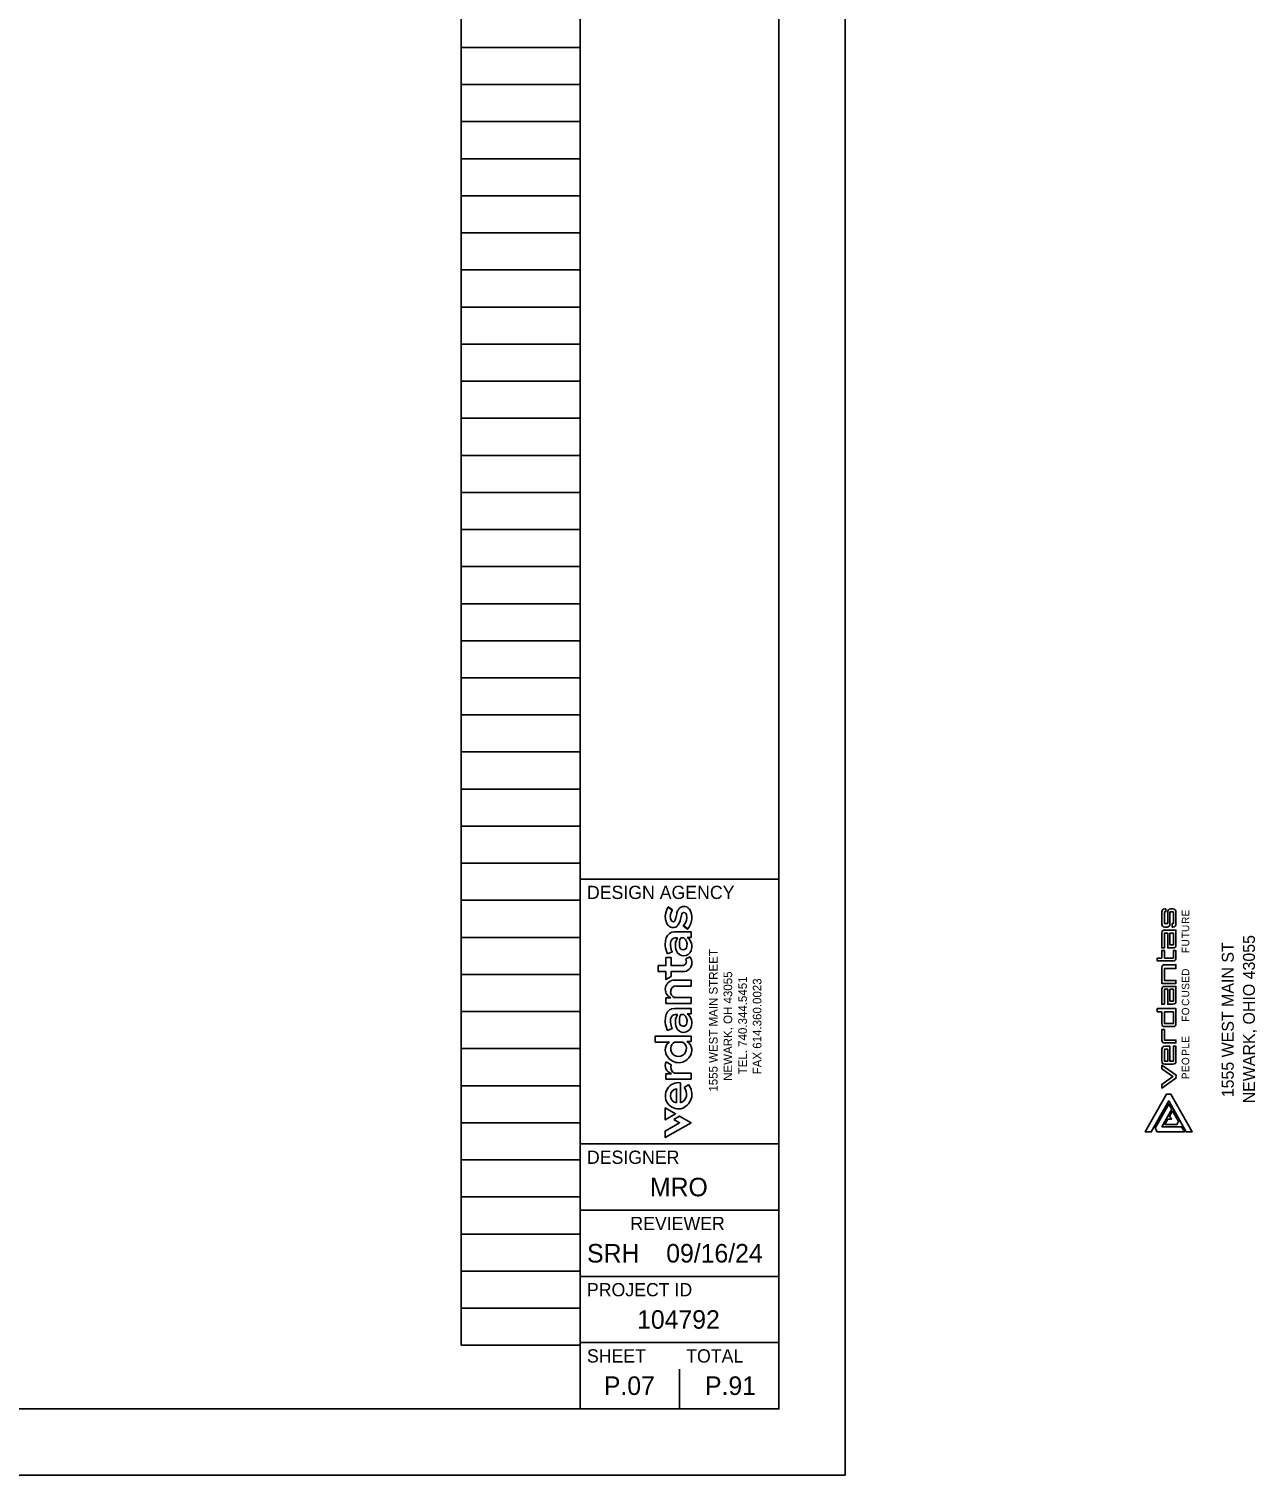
# Model space of a CAD drawing. Extents: x 0 to 37.1, y 0 to 22.
# Drawn here: x 27.83 to 37.11, y 0 to 10.92 of the extents above; entities that cross this region are included whole.
import ezdxf

# ---------------------------------------------------------------- set-up
doc = ezdxf.new("R2010")
doc.units = 0
for name, color, linetype in [('CS-ANNO-TTLB-LOGO', 7, 'Continuous'), ('Default', 7, 'Continuous'), ('SH_Border', 7, 'Continuous'), ('SH_Cut_Line', 7, 'Continuous'), ('SH_Data', 7, 'Continuous'), ('SH_Text', 7, 'Continuous')]:
    doc.layers.add(name, color=color, linetype=linetype)

msp = doc.modelspace()

# ---------------------------------------------------------------- linework, layer by layer
at = {"layer": 'CS-ANNO-TTLB-LOGO'}
for p, q in [((36.423, 4.275), (36.415, 4.275)), ((36.477, 4.275), (36.46, 4.275)), ((36.392, 4.253), (36.392, 4.16)), ((36.499, 4.16), (36.499, 4.253)), ((36.392, 3.98), (36.392, 4.093)), ((36.415, 4.138), (36.432, 4.138)), ((36.392, 3.555), (36.392, 3.668)), ((36.415, 3.387), (36.477, 3.387)), ((36.392, 3.215), (36.392, 3.125)), ((36.499, 3.125), (36.499, 3.238)), ((36.415, 3.103), (36.477, 3.103))]:
    msp.add_line(p, q, dxfattribs=at)
for points in [[(36.437, 4.253), (36.437, 4.166), (36.412, 4.166), (36.412, 4.253), (36.423, 4.253), (36.423, 4.275)], [(36.454, 4.16), (36.454, 4.253), (36.48, 4.253), (36.48, 4.166), (36.471, 4.166), (36.471, 4.138), (36.477, 4.138)], [(36.477, 3.98), (36.437, 3.98), (36.437, 4.093), (36.412, 4.093), (36.412, 3.98), (36.392, 3.98)], [(36.415, 4.115), (36.499, 4.115), (36.499, 4.003)], [(36.358, 3.904), (36.392, 3.904), (36.392, 3.96), (36.412, 3.96), (36.412, 3.904), (36.48, 3.904), (36.48, 3.96), (36.499, 3.96), (36.499, 3.904)], [(36.477, 3.882), (36.358, 3.882), (36.358, 3.904)], [(36.392, 3.831), (36.392, 3.713), (36.499, 3.713), (36.499, 3.735), (36.412, 3.735), (36.412, 3.825), (36.499, 3.825)], [(36.499, 3.825), (36.499, 3.853), (36.415, 3.853)], [(36.477, 3.555), (36.437, 3.555), (36.437, 3.668), (36.412, 3.668), (36.412, 3.555), (36.392, 3.555)], [(36.415, 3.69), (36.499, 3.69), (36.499, 3.578)], [(36.358, 3.522), (36.358, 3.499), (36.392, 3.499), (36.392, 3.409)], [(36.499, 3.409), (36.499, 3.522), (36.358, 3.522)], [(36.499, 3.285), (36.412, 3.285), (36.412, 3.364), (36.392, 3.364), (36.392, 3.285)], [(36.415, 3.263), (36.499, 3.263), (36.499, 3.285)], [(36.499, 3.238), (36.48, 3.238), (36.48, 3.125), (36.454, 3.125), (36.454, 3.238), (36.415, 3.238)]]:
    msp.add_lwpolyline(points, dxfattribs=at)
for points in [[(36.454, 4.093), (36.48, 4.093), (36.48, 4.003), (36.454, 4.003)], [(36.454, 3.668), (36.48, 3.668), (36.48, 3.578), (36.454, 3.578)], [(36.412, 3.499), (36.412, 3.409), (36.48, 3.409), (36.48, 3.499)], [(36.437, 3.215), (36.412, 3.215), (36.412, 3.125), (36.437, 3.125)], [(36.477, 3.009), (36.392, 2.95), (36.392, 2.922), (36.499, 2.997), (36.5, 3.02), (36.393, 3.095), (36.392, 3.068)]]:
    msp.add_lwpolyline(points, close=True, dxfattribs=at)
for centre, start, end in [((36.415, 4.253), 90, 180), ((36.46, 4.253), 90, 180), ((36.477, 4.253), 360, 90), ((36.415, 4.16), 180, 270), ((36.432, 4.16), 270, 0), ((36.477, 4.16), 270, 0), ((36.415, 4.093), 90, 180), ((36.477, 4.003), 270, 360), ((36.415, 3.831), 90, 180), ((36.477, 3.904), 270, 360), ((36.415, 3.668), 90, 180), ((36.477, 3.578), 270, 360), ((36.415, 3.409), 180, 270), ((36.477, 3.409), 270, 0), ((36.415, 3.285), 180, 270), ((36.415, 3.215), 90, 180), ((36.415, 3.125), 180, 270), ((36.477, 3.125), 270, 0)]:
    msp.add_arc(centre, 0.0225, start, end, dxfattribs=at)
at = {"layer": 'Default'}
for p, q in [((36.477, 4.275), (36.46, 4.275)), ((36.392, 4.253), (36.392, 4.16)), ((36.499, 4.16), (36.499, 4.253)), ((36.415, 4.138), (36.432, 4.138)), ((36.415, 3.387), (36.477, 3.387)), ((36.392, 3.215), (36.392, 3.125)), ((36.415, 3.103), (36.477, 3.103)), ((36.342, 2.619), (36.445, 2.802)), ((36.468, 2.762), (36.394, 2.63)), ((36.445, 2.802), (36.468, 2.762)), ((36.394, 2.63), (36.542, 2.63)), ((36.542, 2.63), (36.564, 2.591)), ((36.358, 2.591), (36.342, 2.619)), ((36.564, 2.591), (36.358, 2.591))]:
    msp.add_line(p, q, dxfattribs=at)
for points in [[(36.437, 4.253), (36.437, 4.166), (36.412, 4.166), (36.412, 4.253), (36.423, 4.253), (36.423, 4.275), (36.415, 4.275)], [(36.454, 4.16), (36.454, 4.253), (36.48, 4.253), (36.48, 4.166), (36.471, 4.166), (36.471, 4.138), (36.477, 4.138)], [(36.392, 4.093), (36.392, 3.98), (36.412, 3.98), (36.412, 4.093), (36.437, 4.093), (36.437, 3.98), (36.477, 3.98)], [(36.499, 4.003), (36.499, 4.115), (36.415, 4.115)], [(36.499, 3.904), (36.499, 3.96), (36.48, 3.96), (36.48, 3.904), (36.412, 3.904), (36.412, 3.96), (36.392, 3.96), (36.392, 3.904), (36.358, 3.904), (36.358, 3.882), (36.477, 3.882)], [(36.392, 3.831), (36.392, 3.713), (36.499, 3.713), (36.499, 3.735), (36.412, 3.735), (36.412, 3.825), (36.499, 3.825), (36.499, 3.853), (36.415, 3.853)], [(36.392, 3.668), (36.392, 3.555), (36.412, 3.555), (36.412, 3.668), (36.437, 3.668), (36.437, 3.555), (36.477, 3.555)], [(36.499, 3.578), (36.499, 3.69), (36.415, 3.69)], [(36.499, 3.409), (36.499, 3.522), (36.358, 3.522), (36.358, 3.499), (36.392, 3.499), (36.392, 3.409)], [(36.415, 3.263), (36.499, 3.263), (36.499, 3.285), (36.412, 3.285), (36.412, 3.364), (36.392, 3.364), (36.392, 3.285)], [(36.499, 3.125), (36.499, 3.238), (36.48, 3.238), (36.48, 3.125), (36.454, 3.125), (36.454, 3.238), (36.415, 3.238)]]:
    msp.add_lwpolyline(points, dxfattribs=at)
for points in [[(36.48, 4.093), (36.48, 4.003), (36.454, 4.003), (36.454, 4.093)], [(36.48, 3.668), (36.48, 3.578), (36.454, 3.578), (36.454, 3.668)], [(36.412, 3.499), (36.48, 3.499), (36.48, 3.409), (36.412, 3.409)], [(36.437, 3.215), (36.437, 3.125), (36.412, 3.125), (36.412, 3.215)], [(36.392, 2.95), (36.392, 2.922), (36.499, 2.997), (36.5, 3.02), (36.393, 3.095), (36.392, 3.068), (36.477, 3.009)], [(36.445, 2.825), (36.577, 2.591), (36.622, 2.591), (36.461, 2.876), (36.429, 2.876), (36.268, 2.591), (36.313, 2.591)], [(36.313, 2.591), (36.445, 2.825), (36.577, 2.591), (36.622, 2.591), (36.461, 2.876), (36.429, 2.876), (36.268, 2.591)], [(36.342, 2.619), (36.358, 2.591), (36.564, 2.591), (36.542, 2.63), (36.394, 2.63), (36.468, 2.762), (36.445, 2.802)], [(36.438, 2.687), (36.416, 2.647), (36.507, 2.647), (36.519, 2.67), (36.474, 2.75), (36.452, 2.71), (36.465, 2.687)], [(36.438, 2.687), (36.465, 2.687), (36.452, 2.71), (36.474, 2.75), (36.519, 2.67), (36.507, 2.647), (36.416, 2.647)]]:
    msp.add_lwpolyline(points, close=True, dxfattribs=at)
for centre, start, end in [((36.415, 4.253), 90, 180), ((36.46, 4.253), 90, 180), ((36.477, 4.253), 360, 90), ((36.415, 4.16), 180, 270), ((36.432, 4.16), 270, 0), ((36.477, 4.16), 270, 0), ((36.415, 4.093), 90, 180), ((36.477, 4.003), 270, 0), ((36.415, 3.831), 90, 180), ((36.477, 3.904), 270, 0), ((36.415, 3.668), 90, 180), ((36.477, 3.578), 270, 0), ((36.415, 3.409), 180, 270), ((36.477, 3.409), 270, 0), ((36.415, 3.285), 180, 270), ((36.415, 3.215), 90, 180), ((36.415, 3.125), 180, 270), ((36.477, 3.125), 270, 0)]:
    msp.add_arc(centre, 0.0225, start, end, dxfattribs=at)
at = {"layer": 'SH_Border'}
for p, q in [((32, 0.5), (32, 21.5)), ((32, 4.5), (33.5, 4.5)), ((32, 2.5), (33.5, 2.5)), ((32, 2), (33.5, 2)), ((32, 1.5), (33.5, 1.5)), ((32, 1), (33.5, 1))]:
    msp.add_line(p, q, dxfattribs=at)
msp.add_lwpolyline([(1.5, 21.5), (33.5, 21.5), (33.5, 0.5), (1.5, 0.5)], close=True, dxfattribs=at)
at = {"layer": 'SH_Cut_Line'}
msp.add_lwpolyline([(0, 0), (34, 0), (34, 22), (0, 22)], close=True, dxfattribs=at)
at = {"layer": 'SH_Data'}
for p, q in [((31.1, 0.98), (31.1, 21.14)), ((32, 0.98), (32, 21.14)), ((31.1, 10.78), (32, 10.78)), ((31.1, 10.5), (32, 10.5)), ((31.1, 10.22), (32, 10.22)), ((31.1, 9.94), (32, 9.94)), ((31.1, 9.66), (32, 9.66)), ((31.1, 9.38), (32, 9.38)), ((31.1, 9.1), (32, 9.1)), ((31.1, 8.82), (32, 8.82)), ((31.1, 8.54), (32, 8.54)), ((31.1, 8.26), (32, 8.26)), ((31.1, 7.98), (32, 7.98)), ((31.1, 7.7), (32, 7.7)), ((31.1, 7.42), (32, 7.42)), ((31.1, 7.14), (32, 7.14)), ((31.1, 6.86), (32, 6.86)), ((31.1, 6.58), (32, 6.58)), ((31.1, 6.3), (32, 6.3)), ((31.1, 6.02), (32, 6.02)), ((31.1, 5.74), (32, 5.74)), ((31.1, 5.46), (32, 5.46)), ((31.1, 5.18), (32, 5.18)), ((31.1, 4.9), (32, 4.9)), ((31.1, 4.62), (32, 4.62)), ((31.1, 4.34), (32, 4.34)), ((31.1, 4.06), (32, 4.06)), ((31.1, 3.78), (32, 3.78)), ((31.1, 3.5), (32, 3.5)), ((32.75, 3.5), (32.75, 3.5)), ((31.1, 3.22), (32, 3.22)), ((31.1, 2.94), (32, 2.94)), ((31.1, 2.66), (32, 2.66)), ((31.1, 2.38), (32, 2.38)), ((31.1, 2.1), (32, 2.1)), ((31.1, 1.82), (32, 1.82)), ((31.1, 1.54), (32, 1.54)), ((31.1, 1.26), (32, 1.26)), ((31.1, 0.98), (32, 0.98)), ((32.75, 0.5), (32.75, 0.8)), ((32.375, 0.675), (32.375, 0.675))]:
    msp.add_line(p, q, dxfattribs=at)
at = {"layer": 'SH_Text'}
for p, q in [((32.694, 4.265), (32.663, 4.288)), ((32.728, 4.239), (32.722, 4.208)), ((32.757, 4.197), (32.762, 4.217)), ((32.717, 4.057), (32.733, 4.057)), ((32.759, 4.057), (32.782, 4.057)), ((32.78, 4.149), (32.813, 4.125)), ((32.654, 3.949), (32.658, 3.937)), ((32.831, 3.913), (32.796, 3.897)), ((32.717, 3.478), (32.733, 3.478)), ((32.759, 3.478), (32.782, 3.478)), ((32.654, 3.37), (32.658, 3.358)), ((32.712, 3.27), (32.772, 3.27)), ((32.685, 3.099), (32.648, 3.121)), ((32.757, 2.81), (32.757, 2.963)), ((32.727, 2.918), (32.727, 2.811)), ((32.817, 2.948), (32.784, 2.926))]:
    msp.add_line(p, q, dxfattribs=at)
for points in [[(32.696, 4.267), (32.664, 4.29), (32.663, 4.288)], [(32.694, 4.265), (32.696, 4.267)], [(32.728, 4.239), (32.722, 4.208)], [(32.757, 4.197), (32.762, 4.217)], [(32.807, 4.06), (32.837, 4.06), (32.837, 4.102), (32.712, 4.102)], [(32.807, 4.06), (32.837, 4.06), (32.837, 4.102), (32.712, 4.102)], [(32.717, 4.057), (32.733, 4.057)], [(32.782, 4.057), (32.759, 4.057)], [(32.78, 4.149), (32.778, 4.147), (32.809, 4.122), (32.813, 4.125)], [(32.654, 3.949), (32.658, 3.937)], [(32.658, 3.937), (32.694, 3.951), (32.69, 3.96)], [(32.658, 3.937), (32.694, 3.951), (32.69, 3.96)], [(32.768, 3.847), (32.686, 3.847), (32.686, 3.908), (32.647, 3.908), (32.647, 3.847), (32.589, 3.847), (32.589, 3.802), (32.647, 3.802), (32.647, 3.742), (32.686, 3.765), (32.686, 3.802), (32.776, 3.802)], [(32.768, 3.847), (32.686, 3.847), (32.686, 3.908), (32.647, 3.908), (32.647, 3.847), (32.589, 3.847), (32.589, 3.802), (32.647, 3.802), (32.647, 3.742), (32.686, 3.765), (32.686, 3.802), (32.776, 3.802)], [(32.831, 3.913), (32.796, 3.897)], [(32.726, 3.693), (32.837, 3.693), (32.837, 3.738), (32.713, 3.738)], [(32.726, 3.693), (32.837, 3.693), (32.837, 3.738), (32.713, 3.738)], [(32.684, 3.603), (32.647, 3.603), (32.647, 3.561), (32.837, 3.561), (32.837, 3.607), (32.71, 3.607)], [(32.684, 3.603), (32.647, 3.603), (32.647, 3.561), (32.837, 3.561), (32.837, 3.607), (32.71, 3.607)], [(32.807, 3.482), (32.837, 3.482), (32.837, 3.524), (32.712, 3.524)], [(32.807, 3.482), (32.837, 3.482), (32.837, 3.524), (32.712, 3.524)], [(32.717, 3.478), (32.733, 3.478)], [(32.782, 3.478), (32.759, 3.478)], [(32.673, 3.27), (32.566, 3.27), (32.566, 3.315), (32.837, 3.315), (32.837, 3.274), (32.804, 3.274)], [(32.804, 3.274), (32.837, 3.274), (32.837, 3.315), (32.566, 3.315), (32.566, 3.27), (32.673, 3.27)], [(32.654, 3.37), (32.658, 3.358)], [(32.658, 3.358), (32.694, 3.373), (32.69, 3.382)], [(32.658, 3.358), (32.694, 3.373), (32.69, 3.382)], [(32.712, 3.27), (32.772, 3.27)], [(32.685, 3.099), (32.648, 3.121)], [(32.688, 3.031), (32.647, 3.031), (32.647, 2.99), (32.837, 2.99), (32.837, 3.034), (32.711, 3.034)], [(32.688, 3.031), (32.647, 3.031), (32.647, 2.99), (32.837, 2.99), (32.837, 3.034), (32.711, 3.034)], [(32.757, 2.81), (32.757, 2.963)], [(32.727, 2.811), (32.727, 2.918)], [(32.817, 2.948), (32.784, 2.926)], [(32.642, 2.773), (32.642, 2.682), (32.72, 2.728), (32.642, 2.773)], [(32.706, 2.686), (32.75, 2.66), (32.642, 2.598), (32.642, 2.548), (32.837, 2.66), (32.749, 2.711), (32.706, 2.686)]]:
    msp.add_lwpolyline(points, dxfattribs=at)
for points in [[(32.72, 2.728), (32.642, 2.682), (32.642, 2.773)], [(32.706, 2.686), (32.75, 2.66), (32.642, 2.598), (32.642, 2.548), (32.837, 2.66), (32.749, 2.711)]]:
    msp.add_lwpolyline(points, close=True, dxfattribs=at)
for centre, radius, start, end in [((32.773, 4.217), 0.131, 147.2233, 179.842), ((32.773, 4.217), 0.131, 147.2233, 179.842), ((32.774, 4.215), 0.0948, 148.1233, 178.1135), ((32.774, 4.215), 0.0948, 148.1233, 178.1135), ((32.855, 4.21), 0.13, 154.0447, 167.2149), ((32.855, 4.21), 0.13, 154.0447, 167.2149), ((32.783, 4.245), 0.0493, 52.7092, 154.2166), ((32.783, 4.245), 0.0493, 52.7092, 154.2166), ((32.767, 4.23), 0.0711, 22.8278, 50.7157), ((32.767, 4.23), 0.0711, 22.8278, 50.7157), ((32.756, 4.216), 0.114, 179.0109, 203.56), ((32.756, 4.216), 0.114, 179.0109, 203.56), ((32.713, 4.197), 0.067, 203.3692, 237.807), ((32.713, 4.197), 0.067, 203.3692, 237.807), ((32.75, 4.216), 0.0702, 179.0539, 195.6921), ((32.75, 4.216), 0.0702, 179.0539, 195.6921), ((32.715, 4.206), 0.0335, 193.8561, 223.7191), ((32.715, 4.206), 0.0335, 193.8561, 223.7191), ((32.701, 4.193), 0.0148, 224.7822, 330.4366), ((32.701, 4.193), 0.0148, 224.7822, 330.4366), ((32.641, 4.223), 0.0819, 332.9002, 349.3831), ((32.641, 4.223), 0.0819, 332.9002, 349.3831), ((32.654, 4.216), 0.105, 320.1259, 349.7023), ((32.654, 4.216), 0.105, 320.1259, 349.7023), ((32.855, 4.202), 0.0949, 158.1863, 170.6328), ((32.855, 4.202), 0.0949, 158.1863, 170.6328), ((32.783, 4.232), 0.0165, 26.9165, 163.602), ((32.783, 4.232), 0.0165, 26.9165, 163.602), ((32.712, 4.212), 0.0932, 317.363, 356.9244), ((32.712, 4.212), 0.0932, 317.363, 356.9244), ((32.739, 4.211), 0.0655, 357.0077, 26.3112), ((32.739, 4.211), 0.0655, 357.0077, 26.3112), ((32.713, 4.208), 0.129, 320.5166, 0.4341), ((32.713, 4.208), 0.129, 320.5166, 0.4341), ((32.723, 4.211), 0.12, 359.0192, 22.9257), ((32.723, 4.211), 0.12, 359.0192, 22.9257), ((32.77, 4.015), 0.128, 160.8128, 180.9317), ((32.77, 4.015), 0.128, 160.8128, 180.9317), ((32.71, 4.038), 0.0639, 88.076, 162.8642), ((32.71, 4.038), 0.0639, 88.076, 162.8642), ((32.701, 4.179), 0.0458, 238.9453, 317.6829), ((32.701, 4.179), 0.0458, 238.9453, 317.6829), ((32.719, 4.019), 0.0374, 92.9671, 165.223), ((32.719, 4.019), 0.0374, 92.9671, 165.223), ((32.826, 4), 0.108, 148.3497, 202.4708), ((32.826, 4), 0.108, 148.3497, 202.4708), ((32.853, 4.01), 0.105, 153.8372, 188.8746), ((32.853, 4.01), 0.105, 153.8372, 188.8746), ((32.743, 4.006), 0.0637, 348.1247, 52.3678), ((32.743, 4.006), 0.0637, 348.1247, 52.3678), ((32.757, 3.991), 0.0857, 338.2774, 53.7949), ((32.757, 3.991), 0.0857, 338.2774, 53.7949), ((32.84, 4.016), 0.199, 180.9467, 199.8354), ((32.84, 4.016), 0.199, 180.9467, 199.8354), ((32.745, 4.01), 0.0647, 163.2522, 179.9971), ((32.745, 4.01), 0.0647, 163.2522, 179.9971), ((32.832, 4.014), 0.152, 181.6616, 200.8714), ((32.832, 4.014), 0.152, 181.6616, 200.8714), ((32.781, 3.98), 0.0592, 201.6764, 339.7268), ((32.781, 3.98), 0.0592, 201.6764, 339.7268), ((32.777, 3.995), 0.0281, 182.327, 355.3778), ((32.777, 3.995), 0.0281, 182.327, 355.3778), ((32.77, 3.878), 0.0314, 265.0692, 356.3548), ((32.77, 3.878), 0.0314, 265.0692, 356.3548), ((32.778, 3.866), 0.0642, 267.8641, 1.6213), ((32.778, 3.866), 0.0642, 267.8641, 1.6213), ((32.759, 3.875), 0.0432, 1.8638, 29.9651), ((32.759, 3.875), 0.0432, 1.8638, 29.9651), ((32.748, 3.868), 0.0939, 359.5424, 28.2495), ((32.748, 3.868), 0.0939, 359.5424, 28.2495), ((32.712, 3.668), 0.0703, 88.9896, 246.9111), ((32.712, 3.668), 0.0703, 88.9896, 246.9111), ((32.726, 3.652), 0.0434, 137.3049, 182.9688), ((32.726, 3.652), 0.0434, 137.3049, 182.9688), ((32.73, 3.65), 0.0477, 180.3466, 244.9113), ((32.73, 3.65), 0.0477, 180.3466, 244.9113), ((32.723, 3.65), 0.0433, 86.9739, 132.7421), ((32.723, 3.65), 0.0433, 86.9739, 132.7421), ((32.71, 3.46), 0.0639, 88.076, 162.8642), ((32.71, 3.46), 0.0639, 88.076, 162.8642), ((32.77, 3.436), 0.128, 160.8128, 180.9317), ((32.77, 3.436), 0.128, 160.8128, 180.9317), ((32.84, 3.438), 0.199, 180.9467, 199.8354), ((32.84, 3.438), 0.199, 180.9467, 199.8354), ((32.745, 3.432), 0.0647, 163.2522, 179.9971), ((32.745, 3.432), 0.0647, 163.2522, 179.9971), ((32.832, 3.436), 0.152, 181.6616, 200.8714), ((32.832, 3.436), 0.152, 181.6616, 200.8714), ((32.719, 3.441), 0.0374, 92.9671, 165.223), ((32.719, 3.441), 0.0374, 92.9671, 165.223), ((32.826, 3.421), 0.108, 148.3497, 202.4708), ((32.826, 3.421), 0.108, 148.3497, 202.4708), ((32.853, 3.432), 0.105, 153.8372, 188.8746), ((32.853, 3.432), 0.105, 153.8372, 188.8746), ((32.777, 3.417), 0.0281, 182.327, 355.3778), ((32.777, 3.417), 0.0281, 182.327, 355.3778), ((32.743, 3.428), 0.0637, 348.1247, 52.3678), ((32.743, 3.428), 0.0637, 348.1247, 52.3678), ((32.757, 3.413), 0.0857, 338.2774, 53.7949), ((32.757, 3.413), 0.0857, 338.2774, 53.7949), ((32.781, 3.402), 0.0592, 201.6764, 339.7268), ((32.781, 3.402), 0.0592, 201.6764, 339.7268), ((32.713, 3.211), 0.0714, 124.2843, 181.2723), ((32.713, 3.211), 0.0714, 124.2843, 181.2723), ((32.742, 3.214), 0.1, 182.7719, 2.9779), ((32.742, 3.214), 0.1, 182.7719, 2.9779), ((32.741, 3.219), 0.0586, 119.9007, 175.5797), ((32.741, 3.219), 0.0586, 119.9007, 175.5797), ((32.742, 3.22), 0.0595, 176.4529, 5.055), ((32.742, 3.22), 0.0595, 176.4529, 5.055), ((32.743, 3.219), 0.0588, 6.0666, 60.041), ((32.743, 3.219), 0.0588, 6.0666, 60.041), ((32.775, 3.213), 0.0671, 5.3084, 64.5252), ((32.775, 3.213), 0.0671, 5.3084, 64.5252), ((32.704, 3.092), 0.0628, 152.6524, 255.2929), ((32.704, 3.092), 0.0628, 152.6524, 255.2929), ((32.737, 3.082), 0.0545, 162.1384, 242.0408), ((32.737, 3.082), 0.0545, 162.1384, 242.0408), ((32.742, 2.864), 0.0996, 81.0446, 280.2577), ((32.742, 2.864), 0.0996, 81.0446, 280.2577), ((32.735, 2.864), 0.0543, 98.8378, 261.1622), ((32.735, 2.864), 0.0543, 98.8378, 261.1622), ((32.731, 2.877), 0.072, 290.9232, 42.7391), ((32.731, 2.877), 0.072, 290.9232, 42.7391), ((32.729, 2.876), 0.114, 285.6668, 39.3699), ((32.729, 2.876), 0.114, 285.6668, 39.3699)]:
    msp.add_arc(centre, radius, start, end, dxfattribs=at)

# ---------------------------------------------------------------- texts
at = {"layer": 'Default'}
for s, p in [('E', (36.6, 4.218)), ('R', (36.6, 4.162)), ('U', (36.6, 4.101)), ('T', (36.6, 4.053)), ('U', (36.6, 3.992)), ('F', (36.6, 3.941)), ('D', (36.6, 3.77)), ('E', (36.6, 3.718)), ('S', (36.6, 3.665)), ('U', (36.6, 3.606)), ('C', (36.6, 3.543)), ('O', (36.6, 3.472)), ('F', (36.6, 3.423)), ('E', (36.6, 3.265)), ('L', (36.6, 3.22)), ('P', (36.6, 3.167)), ('O', (36.6, 3.096)), ('E', (36.6, 3.043)), ('P', (36.6, 2.99))]:
    msp.add_text(s, height=0.0563, rotation=90, dxfattribs=at).set_placement(p)
at = {"layer": 'SH_Data'}
for s, height, p in [('DESIGN AGENCY', 0.1, (32.05, 4.35)), ('DESIGNER', 0.1, (32.05, 2.35)), ('MRO', 0.14, (32.526, 2.105)), ('REVIEWER', 0.1, (32.378, 1.85)), ('09/16/24', 0.14, (32.649, 1.605)), ('SRH', 0.14, (32.051, 1.605)), ('PROJECT ID', 0.1, (32.05, 1.35)), ('104792', 0.14, (32.429, 1.105)), ('SHEET', 0.1, (32.05, 0.85)), ('TOTAL', 0.1, (32.8, 0.85)), ('P.07', 0.14, (32.178, 0.605)), ('P.91', 0.14, (32.942, 0.605))]:
    msp.add_text(s, height=height, dxfattribs=at).set_placement(p)
at = {"layer": 'SH_Text'}
for s, height, p in [('NEWARK, OHIO 43055', 0.09, (37.096, 2.807)), ('1555 WEST MAIN STREET', 0.06497, (33.037, 2.895)), ('1555 WEST MAIN ST', 0.09, (36.936, 2.853)), ('NEWARK, OH 43055', 0.06497, (33.147, 2.977)), ('TEL. 740.344.5451', 0.06497, (33.258, 3.026)), ('FAX 614.360.0023', 0.06497, (33.368, 3.026))]:
    msp.add_text(s, height=height, rotation=90, dxfattribs=at).set_placement(p)

doc.saveas('drawing.dxf')
